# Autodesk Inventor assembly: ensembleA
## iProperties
Author: Administrateur
Created: 2002-04
Part Number: ensembleA
Document SubType Name: Assemblage
Designer: Administrateur
Control State: 0
Master: False
Checked Out: False
PropertySet Name: Design Tracking Control
Shininess: 41.0
Angle Display Precision: 2
Document Length Units: 11269
Document Angle Units: 11283
Document Time Units: 11279
Document Mass Units: 11290
Document Length Units Precision: 3
Document Angle Units Precision: 2
Compacted: False
PropertySet Name: _Private Model Information
Density: 0.0
Volumn: 0.0
Area: 0.0
PropertySet Name: Model Information
